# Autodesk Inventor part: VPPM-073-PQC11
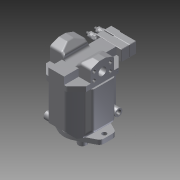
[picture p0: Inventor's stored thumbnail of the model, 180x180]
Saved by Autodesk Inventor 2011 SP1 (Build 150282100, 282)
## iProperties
Created: 2012-03
Part Number: VPPM-073-PQC11
Document SubType Name: Modeling
Designer: khramov
Density: 1 g/cm^3
Mass: 7346.39 g
Surface Area: 3324.14 cm^2
Volume: 7346.39 cm^3
Author: khramov
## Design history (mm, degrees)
derived "Сборка2.iam"
sketch "Эскиз2"
  geometry: C1 r 16 at (52.032, -138.513) reference; 2 further points
  dimensions: "d1" = 122 vertical distance of C1.centre point (91.032, -16.513); "d2" = 39 horizontal distance of C1.centre point (91.032, -16.513)
hole "Отверстие1" sketch "Эскиз2" at (91.032, -16.513) diameter "d3" = 8.566; stored, may be unused: countersink angle "d7" = 90 deg, drill point angle "d9" = 118 deg; dims "d4" = 12, "d5" = 9, "d6" = 2, "d8" = 20
sketch "Эскиз3"
  geometry: L1 (0, 1.5)-(63.5, 1.5); L2 (63.5, 1.5)-(63.5, -5.5); L3 (63.5, -5.5)-(0, -5.5); L4 (0, -5.5)-(0, 1.5); L5 (0, 1.5)-(-1.5, 1.5); L6 (-1.5, 1.5)-(-1.5, -5.5); L7 (-1.5, -5.5)-(0, -5.5); L8 (0, -5.5)-(0, 1.5); 1 further point
  constraints: 16 end point, 4 parallel, 2 horizontal, 2 perpendicular
  dimensions: "d10" = 7 distance between parallel lines of L3 L1
extrude "Выдавливание1" cut sketch "Эскиз3" distance "d11" = 100; taper "d12" = 0 deg
chamfer "Фаска1" distance "d13" = 5; stored, may be unused: second distance "d14" = 2, angle "d15" = 45 deg
node "Твердое тело1"
node "VPPM-073-PQC.ipt:1"
sketch "1.ipt:1"
sketch "1.ipt:2"
